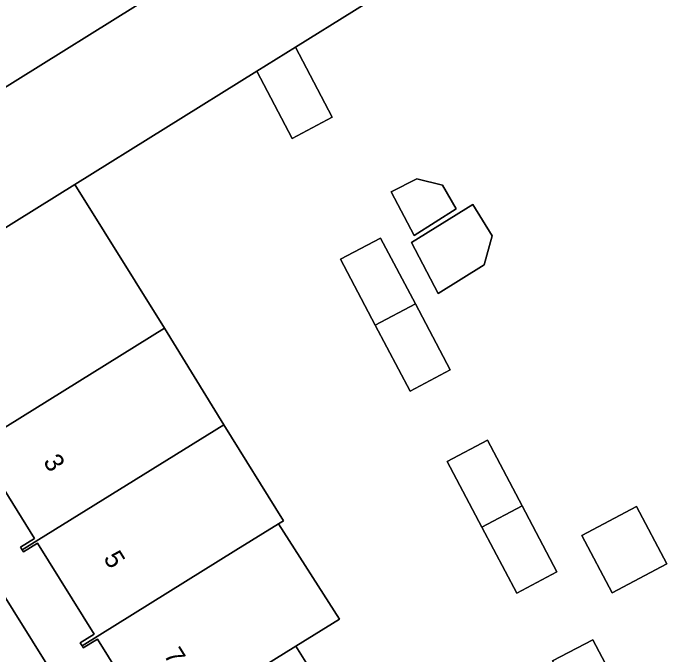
# Model space of a CAD drawing. Extents: x 158835 to 160077, y 386387 to 387778.
# Drawn here: x 159100.34 to 159135.01, y 387194.01 to 387228.05 of the extents above; entities that cross this region are included whole.
import ezdxf

# ---------------------------------------------------------------- set-up
doc = ezdxf.new("R2010")
doc.units = 0
for name, color, linetype in [('IMGEO_Erf', 7, 'Continuous'), ('IMGEO_Groenvoorziening', 7, 'Continuous'), ('IMGEO_Pand', 7, 'Continuous'), ('IMGEO_Pand_nummerreeks', 7, 'Continuous'), ('IMGEO_Voetpad_open', 7, 'Continuous')]:
    doc.layers.add(name, color=color, linetype=linetype)

msp = doc.modelspace()

# ---------------------------------------------------------------- linework, layer by layer
at = {"layer": 'IMGEO_Erf'}
for points in [[(159145.092, 387209.65), (159145.636, 387209.985), (159140.894, 387217.61), (159141.438, 387217.946), (159136.691, 387225.58), (159137.243, 387225.92), (159132.417, 387233.681), (159133.677, 387234.46), (159132.383, 387236.528), (159131.111, 387235.732), (159130.948, 387235.993), (159115.305, 387226.239), (159117.264, 387222.535), (159115.134, 387221.408), (159113.262, 387224.971), (159103.609, 387218.957), (159108.363, 387211.335), (159111.515, 387206.217), (159114.671, 387201.124), (159114.404, 387200.958), (159117.648, 387195.911), (159115.333, 387194.473), (159118.51, 387189.38)], [(159092.033, 387209.677), (159105.563, 387188.033)], [(159107.821, 387190.018), (159104.807, 387194.853), (159104.063, 387194.389), (159103.993, 387194.501), (159103.899, 387194.65), (159104.643, 387195.114), (159101.636, 387199.937), (159100.89, 387199.472), (159100.817, 387199.588), (159100.728, 387199.729), (159101.476, 387200.195), (159098.467, 387205.021)]]:
    msp.add_lwpolyline(points, dxfattribs=at)
for points in [[(159121.609, 387216.254), (159120.384, 387218.573), (159121.749, 387219.269), (159123.11, 387218.934), (159123.834, 387217.675)], [(159122.873, 387213.174), (159121.472, 387215.885), (159124.707, 387217.897), (159125.737, 387216.242), (159125.318, 387214.694)], [(159121.389, 387208.001), (159119.54, 387211.502), (159117.696, 387214.994), (159119.827, 387216.12), (159121.671, 387212.628), (159123.52, 387209.126)], [(159129.174, 387198.419), (159127.043, 387197.294), (159125.199, 387200.786), (159123.355, 387204.279), (159125.486, 387205.404), (159127.33, 387201.911)], [(159134.994, 387198.839), (159132.105, 387197.313), (159130.501, 387200.351), (159133.39, 387201.877)], [(159134.761, 387187.839), (159132.63, 387186.714), (159130.788, 387190.203), (159128.944, 387193.695), (159131.075, 387194.82), (159132.919, 387191.328)]]:
    msp.add_lwpolyline(points, close=True, dxfattribs=at)
at = {"layer": 'IMGEO_Groenvoorziening'}
msp.add_lwpolyline([(159086.64, 387218.318), (159089.329, 387214.01), (159091.098, 387211.176), (159096.184, 387214.339), (159092.832, 387219.703), (159136.296, 387246.811), (159139.679, 387241.4), (159144.958, 387244.669), (159142.098, 387250), (159140.03, 387253.854), (159133.853, 387250), (159109.893, 387235.05), (159087.554, 387221.126)], dxfattribs=at)
msp.add_lwpolyline([(159115.305, 387226.239), (159130.948, 387235.993), (159139.679, 387241.4), (159136.296, 387246.811), (159092.832, 387219.703), (159096.184, 387214.339), (159103.609, 387218.957), (159113.262, 387224.971)], close=True, dxfattribs=at)
at = {"layer": 'IMGEO_Pand'}
for points in [[(159113.262, 387224.971), (159115.134, 387221.408), (159117.264, 387222.535), (159115.305, 387226.239)], [(159120.384, 387218.573), (159121.609, 387216.254), (159123.834, 387217.675), (159123.11, 387218.934), (159121.749, 387219.269)], [(159097.64, 387204.684), (159108.363, 387211.335), (159103.609, 387218.957), (159096.184, 387214.339), (159097.66, 387211.977), (159095.12, 387210.389), (159094.387, 387209.912), (159094.549, 387209.642), (159095.296, 387210.107), (159098.304, 387205.282), (159097.558, 387204.817)], [(159121.472, 387215.885), (159122.873, 387213.174), (159125.318, 387214.694), (159125.737, 387216.242), (159124.707, 387217.897)], [(159121.671, 387212.628), (159119.827, 387216.12), (159117.696, 387214.994), (159119.54, 387211.502)], [(159119.54, 387211.502), (159121.389, 387208.001), (159123.52, 387209.126), (159121.671, 387212.628)], [(159100.817, 387199.588), (159111.515, 387206.217), (159108.363, 387211.335), (159097.64, 387204.684), (159097.719, 387204.555), (159098.467, 387205.021), (159101.476, 387200.195), (159100.728, 387199.729)], [(159114.404, 387200.958), (159114.671, 387201.124), (159111.515, 387206.217), (159100.817, 387199.588), (159100.89, 387199.472), (159101.636, 387199.937), (159104.643, 387195.114), (159103.899, 387194.65), (159103.993, 387194.501), (159112.157, 387199.565)], [(159127.33, 387201.911), (159125.486, 387205.404), (159123.355, 387204.279), (159125.199, 387200.786)], [(159125.199, 387200.786), (159127.043, 387197.294), (159129.174, 387198.419), (159127.33, 387201.911)], [(159130.501, 387200.351), (159132.105, 387197.313), (159134.994, 387198.839), (159133.39, 387201.877)], [(159117.648, 387195.911), (159114.404, 387200.958), (159112.157, 387199.565), (159103.993, 387194.501), (159104.063, 387194.389), (159104.807, 387194.853), (159107.821, 387190.018), (159107.074, 387189.553), (159107.168, 387189.403), (159115.333, 387194.473)], [(159132.919, 387191.328), (159131.075, 387194.82), (159128.944, 387193.695), (159130.788, 387190.203)], [(159110.34, 387184.302), (159118.51, 387189.38), (159115.333, 387194.473), (159107.168, 387189.403), (159107.237, 387189.291), (159107.984, 387189.757), (159110.991, 387184.933), (159110.24, 387184.465)]]:
    msp.add_lwpolyline(points, close=True, dxfattribs=at)
at = {"layer": 'IMGEO_Voetpad_open'}
msp.add_lwpolyline([(159105.563, 387188.033), (159092.033, 387209.677), (159091.098, 387211.176), (159089.329, 387214.01), (159086.64, 387218.318)], dxfattribs=at)

# ---------------------------------------------------------------- texts
at = {"layer": 'IMGEO_Pand_nummerreeks'}
for s, rotation, p in [('3', 301.9424, (159101.907, 387204.268)), ('5', 301.9422, (159105.102, 387199.141)), ('7', 301.9422, (159108.298, 387194.015))]:
    msp.add_text(s, height=1, rotation=rotation, dxfattribs=at).set_placement(p)

doc.saveas('drawing.dxf')
